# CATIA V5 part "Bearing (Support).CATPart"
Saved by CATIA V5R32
Part number: Bearing (Support)
Bounding box of the stored display mesh (mm): x -270 to 10, y -39.842 to 39.842, z -34.808 to 139.842
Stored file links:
  D:\PROJECTS\Project 2022\CATIA V5 6R 2022\Resources\Part Files\c16_catia_v5_6r2022_prt\Universal Joint-(Fig16-49)\Bearing (Support).CATPart
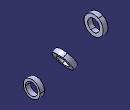
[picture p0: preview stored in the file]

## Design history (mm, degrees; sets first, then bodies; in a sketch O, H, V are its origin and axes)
Body1 (main body)
  Sketch1 on yz-plane, origin (0, 0, 0), H (0, 1, 0), V (0, 0, 1)
    circle A1 centre (0, 0) radius 25
    circle A2 centre (0, 0) radius 35
    radius A1 = 25
    radius A2 = 35
  Pad1: profile Sketch1, direction (1, 0, 0), length 10, mirrored extent
  Sketch2 on zx-plane, origin (0, 0, 0), H (-1, 0, 0), V (0, 0, 1)
    construction line L1 (0, 0) -> (60, 0)
    construction line L2 (60, 0) -> (194.1972, 77.4788)
    line L3 (107.5, 56.2917) -> (124.8205, 66.2917)
    line L4 (124.8205, 66.2917) -> (117.3205, 79.282)
    line L5 (117.3205, 79.282) -> (100, 69.282)
    point P6 (100, 69.282)
    line L6 (100, 69.282) -> (107.5, 56.2917)
    angle L2 L1 = 30
    distance L6 L4 = 20
    length L6 = 15
    distance L3 L2 = 25
    distance P6 V = 100
    length L1 = 60
    horizontal: L1 H
    perpendicularity: L4 L3
    parallelism: L5 L2, L6 L4
  Sketch3 on zx-plane, origin (0, 0, 0), H (-1, 0, 0), V (0, 0, 1)
    line L1 (60, 0) -> (221.9169, 93.4828)
    point P1 (60, 0)
    reference projected line E1 (107.5, 56.2917) -> (124.8205, 66.2917) from Sketch2.L3
    reference projected line E2 (107.5, 56.2917) -> (124.8205, 66.2917) from Sketch2.L3
    distance E2 L1 = 25
    coincidence: P1 H
    parallelism: L1 E1
  Shaft1: profile Sketch2, axis Sketch3.L1, angle 360
  Sketch4 on zx-plane, origin (0, 0, 0), H (-1, 0, 0), V (0, 0, 1)
    construction line L1 (188.3301, 100) -> (395.6544, 100)
    point P3 (260, 132.5)
    line L2 (270, 140) -> (270, 125)
    line L3 (270, 125) -> (250, 125)
    line L4 (250, 125) -> (250, 140)
    line L5 (250, 140) -> (270, 140)
    distance L1 H = 100
    length L5 = 20
    length L4 = 15
    distance L1 L3 = 25
    distance L4 V = 250
    horizontal: L1 H, L3 H, L5 H
    vertical: L2 V, L4 V
    equidistance: L2 L4 P3, L3 L5 P3
  Sketch5 on zx-plane, origin (0, 0, 0), H (-1, 0, 0), V (0, 0, 1)
    line L1 (210.3804, 100) -> (348.9415, 100)
    reference projected line E1 (250, 125) -> (270, 125) from Sketch4.L3
    distance L1 E1 = 25
    horizontal: L1 H
  Shaft2: profile Sketch4, axis Sketch5.L1, angle 360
